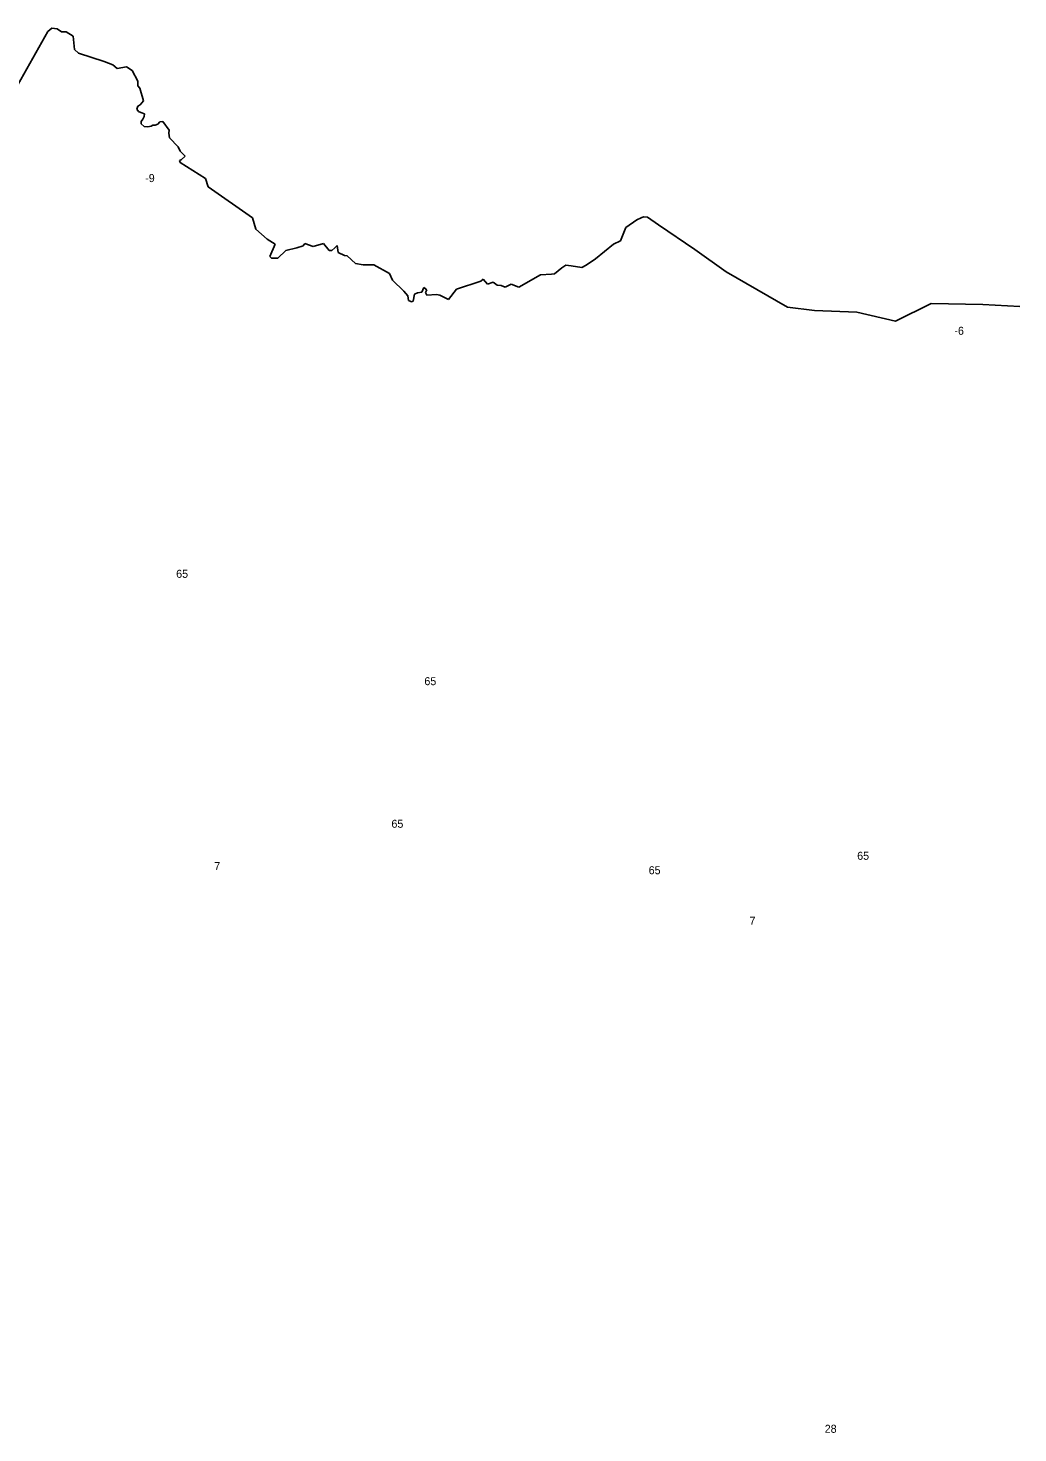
# Model space of a CAD drawing. Extents: x -772472 to -767535, y -969581 to -965387.
# Drawn here: x -771238 to -770002, y -967437 to -965681 of the extents above; entities that cross this region are included whole.
import ezdxf

# ---------------------------------------------------------------- set-up
doc = ezdxf.new("R2010")
doc.units = 0
doc.layers.add('Vrstva 13', color=7, linetype='Continuous')
doc.layers.add('Vrstva 24', color=7, linetype='Continuous')

msp = doc.modelspace()

# ---------------------------------------------------------------- linework, layer by layer
at = {"layer": 'Vrstva 13'}
for p, q in [((-771213.27, -965685.71), (-771207.95, -965681.35)), ((-771207.95, -965681.35), (-771201.39, -965682.45)), ((-771201.39, -965682.45), (-771196.19, -965686.18)), ((-771298.48, -965836.86), (-771213.27, -965685.71)), ((-771196.19, -965686.18), (-771190.43, -965686.07)), ((-771190.43, -965686.07), (-771181.38, -965691.49)), ((-771181.38, -965691.49), (-771179.69, -965708)), ((-771179.69, -965708), (-771174.94, -965712.86)), ((-771174.94, -965712.86), (-771142.73, -965723.15)), ((-771142.73, -965723.15), (-771131.94, -965727.39)), ((-771131.94, -965727.39), (-771126.74, -965731.91)), ((-771126.74, -965731.91), (-771114.76, -965729.65)), ((-771114.76, -965729.65), (-771107.98, -965734.4)), ((-771107.98, -965734.4), (-771100.74, -965747.74)), ((-771100.74, -965747.74), (-771100.74, -965753.39)), ((-771100.74, -965753.39), (-771098.26, -965756.56)), ((-771098.26, -965756.56), (-771093.51, -965772.39)), ((-771100.74, -965778.95), (-771101.87, -965782.79)), ((-771101.87, -965782.79), (-771100.07, -965785.5)), ((-771098.03, -965777.36), (-771100.74, -965778.95)), ((-771100.07, -965785.5), (-771096.9, -965786.64)), ((-771093.51, -965772.39), (-771098.03, -965777.36)), ((-771096.9, -965786.64), (-771092.38, -965788.44)), ((-771094.64, -965795), (-771096.67, -965797.94)), ((-771096.67, -965797.94), (-771096.45, -965801.11)), ((-771096.45, -965801.11), (-771092.83, -965804.27)), ((-771092.83, -965791.61), (-771094.64, -965795)), ((-771092.38, -965788.44), (-771092.83, -965791.61)), ((-771092.83, -965804.27), (-771088.31, -965804.72)), ((-771088.31, -965804.72), (-771084.24, -965803.82)), ((-771084.24, -965803.82), (-771081.98, -965802.69)), ((-771081.98, -965802.69), (-771079.04, -965802.69)), ((-771079.04, -965802.69), (-771075.65, -965801.33)), ((-771075.65, -965801.33), (-771073.39, -965798.62)), ((-771073.39, -965798.62), (-771069.55, -965798.17)), ((-771069.55, -965798.17), (-771061.64, -965809.02)), ((-771061.64, -965809.02), (-771062.1, -965812.64)), ((-771062.1, -965812.64), (-771061.2, -965818.3)), ((-771061.2, -965818.3), (-771050.57, -965829.6)), ((-771050.57, -965829.6), (-771048.09, -965835.03)), ((-771048.09, -965835.03), (-771041.53, -965841.36)), ((-771046.5, -965846.11), (-771048.54, -965846.79)), ((-771048.54, -965846.79), (-771048.09, -965849.28)), ((-771048.09, -965849.28), (-771016.44, -965869.4)), ((-771041.53, -965841.36), (-771046.5, -965846.11)), ((-771016.44, -965869.4), (-771012.83, -965879.8)), ((-771012.83, -965879.8), (-770957.68, -965918.24)), ((-770957.68, -965918.24), (-770953.38, -965932.49)), ((-770491.36, -965930.33), (-770477.79, -965921.06)), ((-770477.79, -965921.06), (-770472.37, -965918.35)), ((-770472.37, -965918.35), (-770469.43, -965916.99)), ((-770469.43, -965916.99), (-770464.47, -965917.78)), ((-770464.47, -965917.78), (-770450.45, -965927.05)), ((-770450.45, -965927.05), (-770405.47, -965958.03)), ((-770953.38, -965932.49), (-770939.37, -965945.15)), ((-770939.37, -965945.15), (-770929.2, -965951.48)), ((-770497.91, -965947.29), (-770491.36, -965930.33)), ((-770929.2, -965951.48), (-770935.98, -965966.63)), ((-770925.8, -965968.89), (-770916.08, -965959.39)), ((-770916.08, -965959.39), (-770902.06, -965955.78)), ((-770902.06, -965955.78), (-770894.38, -965953.29)), ((-770894.38, -965953.29), (-770892.12, -965950.57)), ((-770892.12, -965950.57), (-770881.72, -965954.19)), ((-770881.72, -965954.19), (-770869.06, -965950.57)), ((-770869.06, -965950.57), (-770862.06, -965959.17)), ((-770862.06, -965959.17), (-770858.67, -965959.17)), ((-770858.67, -965959.17), (-770854.6, -965956)), ((-770854.6, -965956), (-770851.66, -965953.06)), ((-770851.66, -965953.06), (-770850.53, -965961.88)), ((-770850.53, -965961.88), (-770842.62, -965965.5)), ((-770529.1, -965969.68), (-770506.95, -965951.36)), ((-770506.95, -965951.36), (-770497.91, -965947.29)), ((-770405.47, -965958.03), (-770366.14, -965986.07)), ((-770935.98, -965966.63), (-770933.72, -965968.66)), ((-770933.72, -965968.66), (-770925.8, -965968.89)), ((-770842.62, -965965.5), (-770839.45, -965965.95)), ((-770839.45, -965965.95), (-770828.83, -965975.45)), ((-770828.83, -965975.45), (-770819.34, -965977.03)), ((-770819.34, -965977.03), (-770806.23, -965977.03)), ((-770806.23, -965977.03), (-770786.56, -965988.11)), ((-770571.37, -965980.98), (-770566.18, -965977.59)), ((-770566.18, -965977.59), (-770559.62, -965978.5)), ((-770559.62, -965978.5), (-770546.28, -965980.31)), ((-770546.28, -965980.31), (-770540.86, -965977.59)), ((-770540.86, -965977.59), (-770529.1, -965969.68)), ((-770786.56, -965988.11), (-770782.95, -965996.24)), ((-770782.95, -965996.24), (-770768.49, -966010.04)), ((-770702.71, -966007.66), (-770672.42, -965997.71)), ((-770672.42, -965997.71), (-770669.48, -965995)), ((-770669.48, -965995), (-770664.05, -966001.11)), ((-770625.18, -966004.95), (-770598.05, -965989.8)), ((-770598.05, -965989.8), (-770584.26, -965988.67)), ((-770584.26, -965988.67), (-770580.42, -965988.22)), ((-770580.42, -965988.22), (-770571.37, -965980.98)), ((-770366.14, -965986.07), (-770289.51, -966030.16)), ((-770768.49, -966010.04), (-770763.46, -966015.89)), ((-770763.46, -966015.89), (-770762.61, -966021.88)), ((-770757.07, -966022.62), (-770755.32, -966013.91)), ((-770755.32, -966013.91), (-770751.53, -966011.99)), ((-770751.53, -966011.99), (-770746.05, -966011.14)), ((-770746.05, -966011.14), (-770743.68, -966005.43)), ((-770743.68, -966005.43), (-770739.78, -966008.26)), ((-770739.78, -966008.26), (-770741.42, -966011.54)), ((-770741.42, -966011.54), (-770739.72, -966014.93)), ((-770739.72, -966014.93), (-770728.02, -966014.22)), ((-770728.02, -966014.22), (-770723.5, -966014.9)), ((-770723.5, -966014.9), (-770712.65, -966020.55)), ((-770712.65, -966020.55), (-770702.71, -966007.66)), ((-770664.05, -966001.11), (-770657.27, -965998.84)), ((-770657.27, -965998.84), (-770652.07, -966002.46)), ((-770652.07, -966002.46), (-770647.1, -966002.91)), ((-770647.1, -966002.91), (-770642.13, -966004.95)), ((-770642.13, -966004.95), (-770634.67, -966001.33)), ((-770634.67, -966001.33), (-770625.18, -966004.95)), ((-770762.61, -966021.88), (-770760.74, -966022.67)), ((-770760.74, -966022.67), (-770759.05, -966023.18)), ((-770759.05, -966023.18), (-770757.07, -966022.62)), ((-770289.51, -966030.16), (-770256.06, -966034.35)), ((-770154.57, -966047.47), (-770110.04, -966025.53)), ((-770110.04, -966025.53), (-770045.85, -966026.9)), ((-770045.85, -966026.9), (-769999.51, -966029.38)), ((-770256.06, -966034.35), (-770203.17, -966036.16)), ((-770203.17, -966036.16), (-770154.57, -966047.47))]:
    msp.add_line(p, q, dxfattribs=at)

# ---------------------------------------------------------------- texts
at = {"layer": 'Vrstva 24'}
for s, p in [('-9', (-771091.574, -965873.75)), ('-6', (-770081.194, -966064.55)), ('65', (-771052.89, -966368.18)), ('65', (-770742.97, -966502.35)), ('65', (-770784.1, -966680.48)), ('65', (-770202.57, -966720.5)), ('7', (-771005.356, -966733.43)), ('65', (-770462.91, -966738.54)), ('7', (-770337.046, -966801.72)), ('28', (-770243.106, -967436.42))]:
    msp.add_text(s, height=10, dxfattribs=at).set_placement(p)

doc.saveas('drawing.dxf')
